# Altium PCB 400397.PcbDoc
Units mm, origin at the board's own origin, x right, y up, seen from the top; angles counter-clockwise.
Board outline 21 x 52.5 mm, 2 copper layers (Top Layer, Bottom Layer), stack 0.971 mm thick; 11 components, 17 nets, 46 pads, 17 vias.
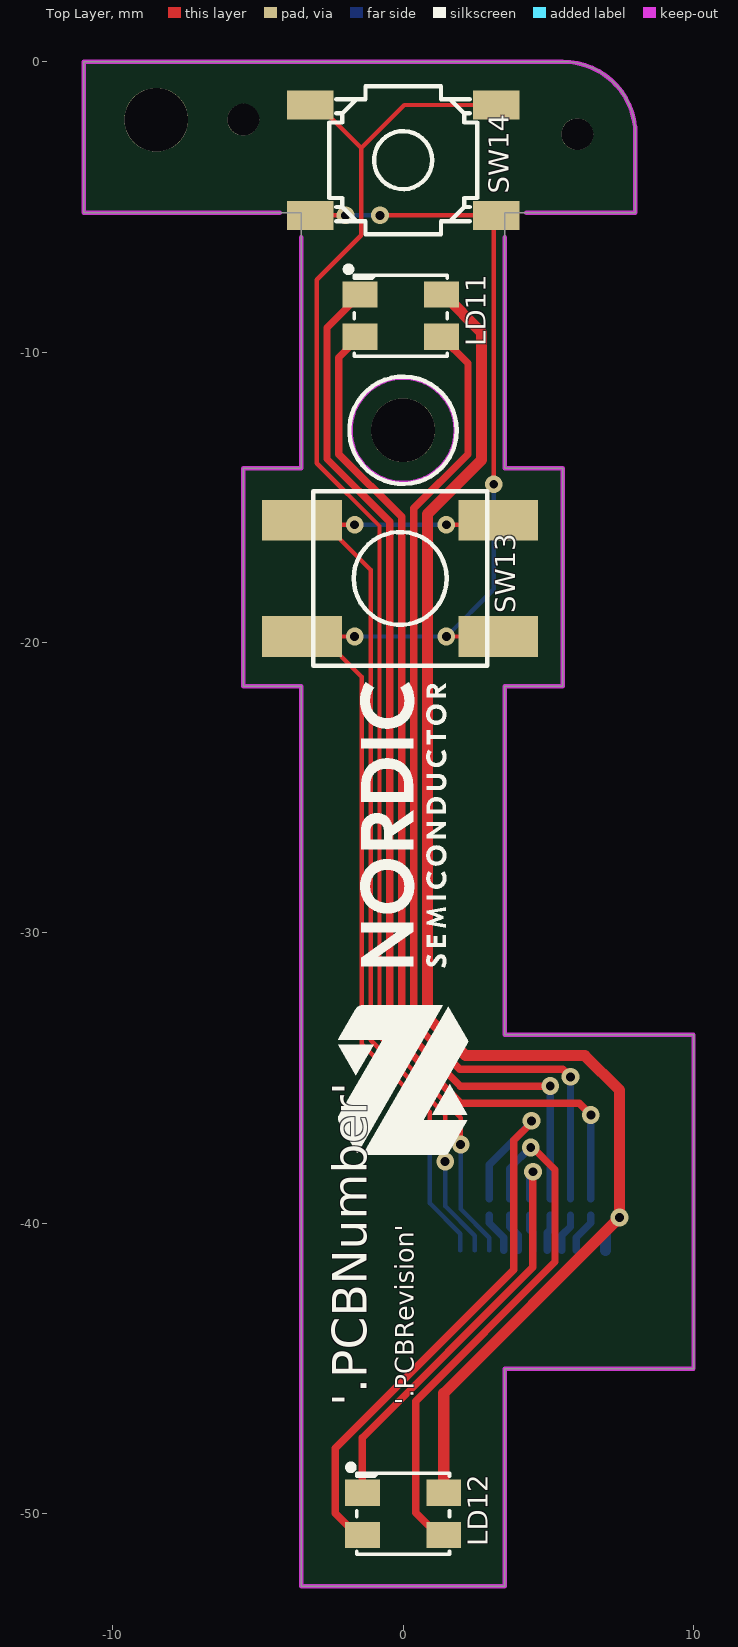
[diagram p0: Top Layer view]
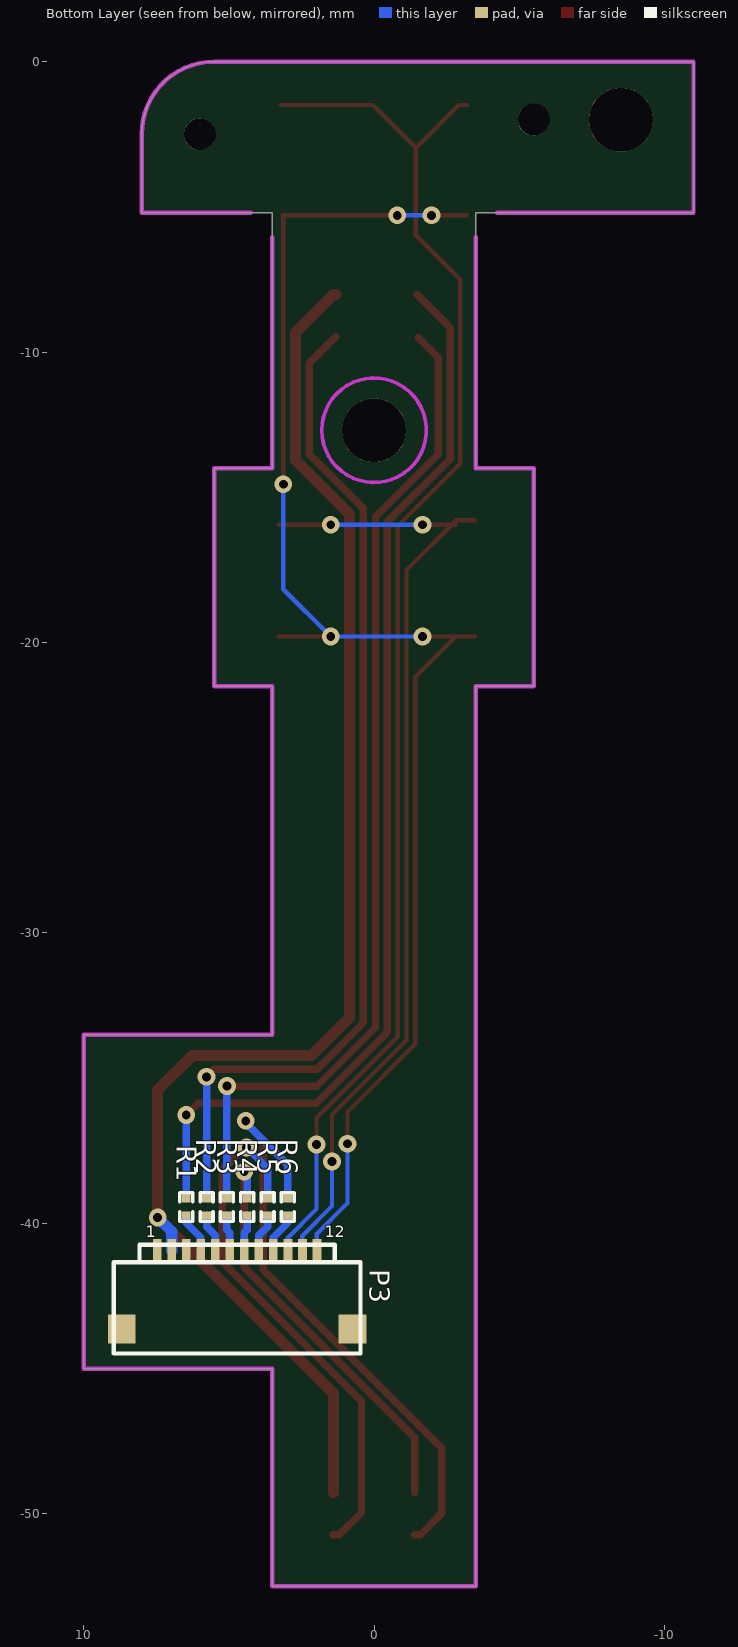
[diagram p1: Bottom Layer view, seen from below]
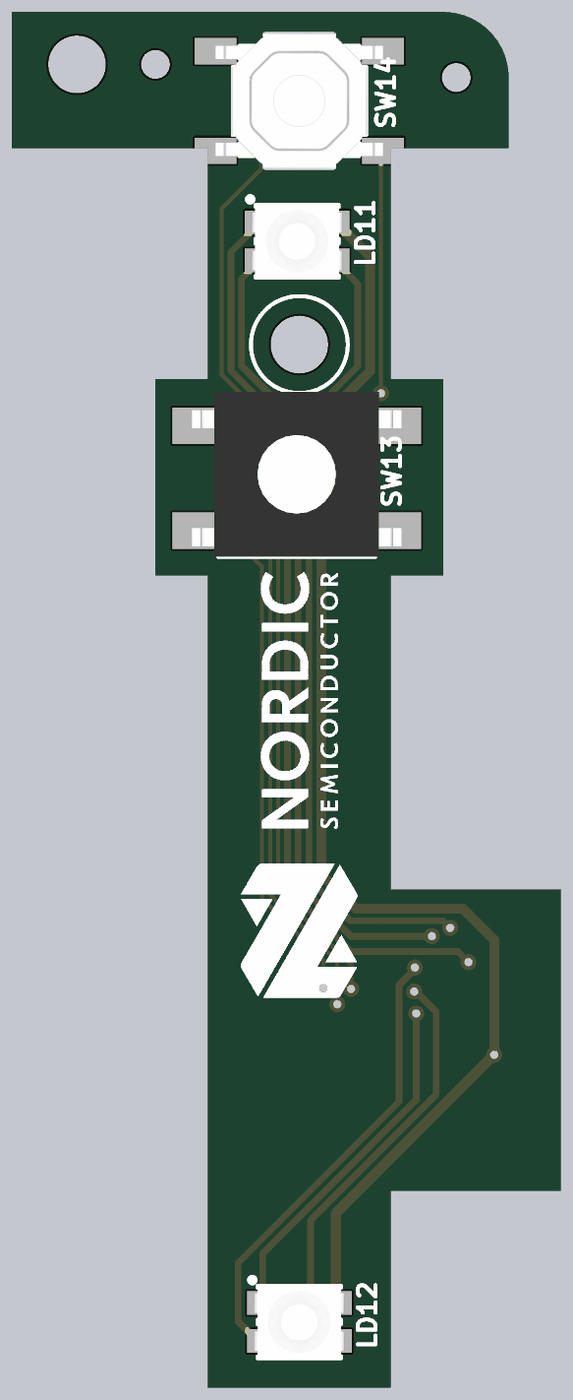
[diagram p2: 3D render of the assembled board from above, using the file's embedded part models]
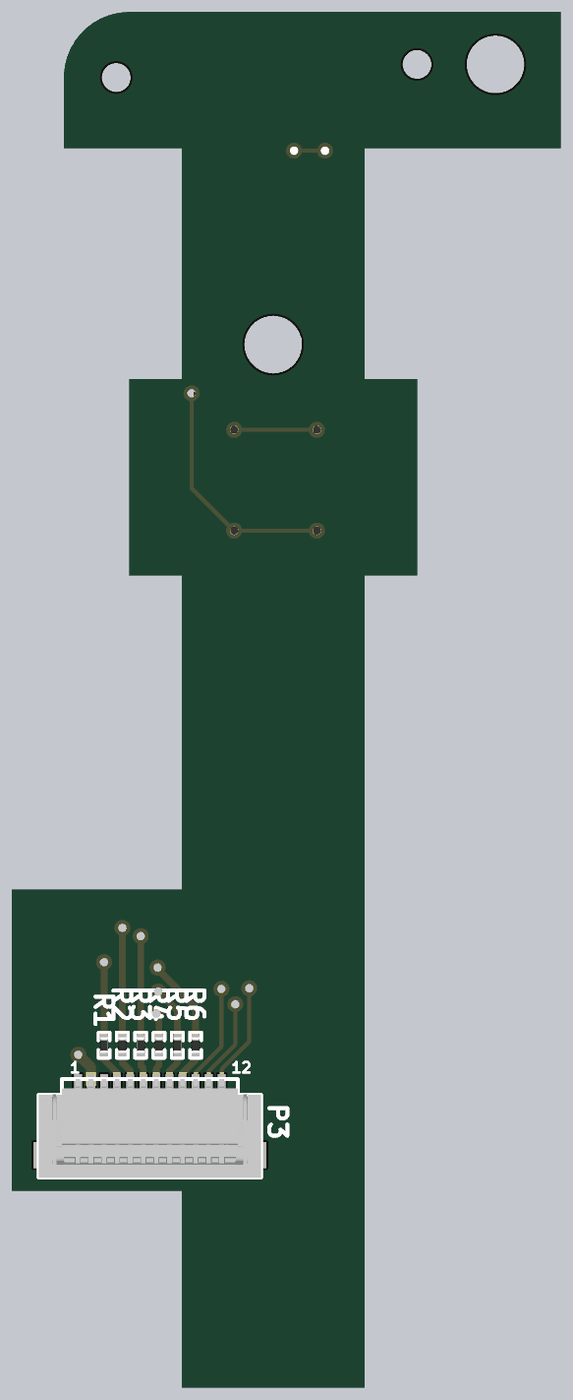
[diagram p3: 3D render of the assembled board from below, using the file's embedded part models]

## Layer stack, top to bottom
Top Solder: solder mask 0.0102, Solder Resist, Dk 3.5
Top Layer: signal copper 0.0356
Dielectric1: core 0.9, FR-4, Dk 4.8
Bottom Layer: signal copper 0.0356
Bottom Solder: solder mask 0.0102, Solder Resist, Dk 3.5

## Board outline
-3.5,-52.5 -3.5,-21.5 -5.5,-21.5 -5.5,-14 -3.5,-14 -3.5,-5.2 -11,-5.2 -11,0 5.5,0 cw(c5.5,-2.5) 8,-2.5 8,-5.2 3.5,-5.2 3.5,-14 5.5,-14 5.5,-21.5 3.5,-21.5 3.5,-33.5 10,-33.5 10,-45 3.5,-45 3.5,-52.5

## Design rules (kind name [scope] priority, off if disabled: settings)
Clearance ANT_Clerance [InNet('ANT')] p1: gap=0.127 ignorepadtopadclearanceinfootprint=FALSE except(0: Arc-Hole Track-Hole SMDPad-Hole THPad-Hole Via-Hole Fill-Hole Poly-Hole Region-Hole Text-Hole)
Clearance Polygon_Clearance [(InNamedPolygon('Top_Layer-GND')) or (InNamedPolygon('Bottom_Layer-GND'))] p2: gap=0.254 ignorepadtopadclearanceinfootprint=FALSE except(0: Arc-Hole Track-Hole SMDPad-Hole THPad-Hole Via-Hole Fill-Hole Poly-Hole Region-Hole Text-Hole)
Clearance [All] p3: gap=0.152 ignorepadtopadclearanceinfootprint=FALSE except(0: Arc-Hole Track-Hole SMDPad-Hole THPad-Hole Via-Hole Fill-Hole Poly-Hole Region-Hole Text-Hole)
ComponentClearance [All] p1 off: gap=0.254 collisioncheckmode=3 verticalgap=0.254 showdistances=FALSE
DiffPairsRouting [All] p1: maxlimit=0.15 minlimit=0.15 mostfreqgap=0.15 toplayer_minwidth=0.381 toplayer_maxwidth=0.381 toplayer_prefwidth=0.381 bottomlayer_minwidth=0.381 bottomlayer_maxwidth=0.381 bottomlayer_prefwidth=0.381 maxuncoupledlength=12.7
FabricationTestPointUsage TestPointUsage [All] p1: valid=0 allowmultiple=FALSE
FabricationTestpoint Testpoint [All] p1: side=3 testpointundercomponent=TRUE minsize=1.016 maxsize=2.54 preferedsize=1.524 minholesize=0 maxholesize=1.016 preferedholesize=0.813 testpointgrid=0.025 allowsidetop=TRUE allowsidebottom=TRUE usegrid=TRUE gridtolerance=0
Height [All] p1 off: minheight=0 maxheight=25.4 prefheight=12.7
HoleSize [All] p1: absolutevalues=TRUE maxlimit=5 minlimit=0.305 maxpercent=80.000 minpercent=20.000
MinimumAnnularRing [All] p1 off: minimumring=0.152
PolygonConnect PolygonConnect_1 [isVia and innet(gnd)] p1: connectstyle=Direct reliefconductorwidth=0.254 reliefentries=4 polygonreliefangle="90 Angle" airgapwidth=0.254
PolygonConnect [All] p2: connectstyle=Relief reliefconductorwidth=0.254 reliefentries=4 polygonreliefangle="90 Angle" airgapwidth=0.254
RoutingVias [All] p1: holewidth=0.305 width=0.61 viastyle="Through Hole" minholewidth=0.305 minwidth=0.61 maxholewidth=0.711 maxwidth=1.27
SilkToSolderMaskClearance SilkscreenOverComponentPads [IsPad] p1: minsilkscreentomaskgap=0.254 clearancetoexposedcopper=TRUE
SolderMaskExpansion [All] p1: expansion=0.076
Width [All] p1: maxlimit=2.54 minlimit=0.152 preferedwidth=0.152
23 further rules are at their usual default settings.

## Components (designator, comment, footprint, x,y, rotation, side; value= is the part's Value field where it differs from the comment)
LD11 "LED RGB" L3528_RGB -0.082,-8.749 r180 top locked
LD12 "LED RGB" L3528_RGB 0,-50 r180 top
P3 "FPC-12, 0.5mm" 10051922-1210ELF 4.716,-40.934 r180 bottom
R1 "1k" RESC0603X03L_C 6.466,-39.434 r270 bottom
R2 "470R" RESC0603X03L_C 5.766,-39.434 r270 bottom
R3 "470R" RESC0603X03L_C 5.066,-39.434 r270 bottom
R4 "1k" RESC0603X03L_C 4.366,-39.434 r270 bottom
R5 "470R" RESC0603X03L_C 3.666,-39.434 r270 bottom
R6 "470R" RESC0603X03L_C 2.966,-39.434 r270 bottom
SW13 "PB SW" Switch-PB-6.2x6.3mm-SMD -0.1,-17.794 r0 top locked
SW14 "PB SW" Switch-PB-5.1x5.1mm-SMD 0,-3.394 r180 top

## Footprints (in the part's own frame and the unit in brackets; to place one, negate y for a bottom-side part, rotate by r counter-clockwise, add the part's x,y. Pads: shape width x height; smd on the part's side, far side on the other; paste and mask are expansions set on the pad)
10051922-1210ELF [mm]
  rect 0.95x1 smd: 0(-3.975,-2.7) 0(3.975,-2.7)
  rect 0.3x0.8 smd: 1(-2.75,0) 2(-2.25,0) 3(-1.75,0) 4(-1.25,0) 5(-0.75,0) 6(-0.25,0) 7(0.25,0) 8(0.75,0) 9(1.25,0) 10(1.75,0) 11(2.25,0) 12(2.75,0)
  silkscreen extent -4.25,-3.55 4.25,0.2, body extent -4.25,-3.55 4.25,0.2, height 1.27
L3528_RGB [mm]
  rect 1.2x0.9 smd: 1(1.4,-0.725) 2(-1.4,0.725) 3(1.4,0.725) 4(-1.4,-0.725)
  silkscreen extent -1.6,-1.7 1.9,1.4, body extent -1.74,-1.39 1.76,1.41, height 1.86
RESC0603X03L_C [mm] "Chip Resistor, 2-Leads, Body 0.6x0.3mm, IPC High Density"
  rect 0.27x0.3 smd: 1(-0.285,0) 2(0.285,0)
  silkscreen extent -0.49,-0.22 0.49,0.22, body extent -0.3,-0.15 0.3,0.15, height 0.23
Switch-PB-5.1x5.1mm-SMD [mm] "5.1×5.1mm TACT Switch"
  rect 1.6x1 smd: 1(-3.2,1.9) 1(3.2,1.9) 2(-3.2,-1.9) 2(3.2,-1.9)
  silkscreen extent -2.56,-2.55 2.54,2.55, body extent -3.3,-2.6 3.2,7.2, height 1.5
Switch-PB-6.2x6.3mm-SMD [mm] "6.2×6.5mm TACT Switch, without ground connector"
  rect 2.75x1.4 smd: 1(-3.375,2) 1(3.375,2) 2(-3.375,-2) 2(3.375,-2)
  silkscreen extent -3,-3 3,3, body extent -4,-3 4,3.3, height 3.1

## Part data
LD11 LD12: library part AAA3528LSEEZGKQBKS, "3.5 x 2.8 mm Surface Mount RGB LED", Manufacturer="Kingbright Company LLC", Part number IPS=N.A., Supplier Part Number 1=754-1967-1-ND
P3: library part 10051922-1210ELF, "0.5mm pitch, bottom side contact, side entry SMD FPC connector", Manufacturer=FCI, Part number IPS=N.A., Supplier Part Number 1=609-1236-1-ND
R1 R4: library part R0201-1k0, "Resistor, ±1%, 0.05W", Part number IPS=N.A.
R2 R3 R5 R6: library part R0201-470, "Resistor, ±1%, 0.05W", Part number IPS=N.A.
SW13: library part Switch-PB-6.2x6.3mm-SMD, "Tactile Switch, SPNO, SMD, 160gf, 6.2x6.3x2.5mm", Manufacturer=Dailywell, Manufacturer Part Number=TS604VM1-025BR-R, Part number IPS=00000007812
SW14: library part Switch-PB-5.1x5.1mm-SMD, "Tactile Switch, SPNO, SMD, 160gf, 5.1x5.1x1.5mm", Manufacturer="C&K Components", Manufacturer Part Number="PTS525 SM15 SMTR2 LFS", Part number IPS=N.A., Supplier Part Number 1=CKN9104CT-ND

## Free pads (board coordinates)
  round 2.2 hole 2.2 unplated: 0(-8.5,-2) 0(0,-12.694)
  round 1.1 hole 1.1 unplated: 0(-5.5,-2) 0(6,-2.5)

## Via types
v1: diameter 0.61, hole 0.305, Top Layer to Bottom Layer, tented both sides, 17 vias

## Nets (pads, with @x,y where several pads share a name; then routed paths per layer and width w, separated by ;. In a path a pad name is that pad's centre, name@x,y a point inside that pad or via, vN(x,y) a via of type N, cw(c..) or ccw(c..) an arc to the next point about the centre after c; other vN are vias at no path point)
COL_B: P3.12 SW13.2 SW14.1 | length 51.4
  Top Layer w0.152: SW13.2@-3.475,-19.794 SW13.2@-2.813,-19.794 ; SW14.1@-3.2,-5.294 v1(-1.981,-5.294) ; v1(-1.669,-19.794) SW13.2@-2.813,-19.794 ; v1(-0.798,-5.294) SW14.1@3.122,-5.294 ; v1(0.914,-37.262) 0.914,-36.163 -1.422,-33.826 -1.422,-21.185 SW13.2@-2.813,-19.794 ; v1(1.491,-19.794) SW13.2@3.275,-19.794 ; v1(3.122,-14.552) SW14.1@3.122,-5.294 ; SW14.1@3.148,-5.294 SW14.1@3.122,-5.294
  Bottom Layer w0.152: v1(-1.981,-5.294) v1(-0.798,-5.294) ; v1(-1.669,-19.794) v1(1.491,-19.794) 3.122,-18.163 v1(3.122,-14.552) ; v1(0.914,-37.262) 0.914,-39.302 1.966,-40.354 P3.12
GND: P3.1
LED2_B: P3.9 R6.2 | length 1.4
  Bottom Layer w0.254: R6.2 2.966,-39.989 3.466,-40.489 P3.9
LED2_G: P3.8 R5.2 | length 1.3
  Bottom Layer w0.254: R5.2 3.666,-40.114 3.966,-40.414 P3.8
LED2_R: P3.7 R4.2 | length 1.3
  Bottom Layer w0.254: R4.2 4.366,-40.215 4.466,-40.315 P3.7
LED3_B: P3.6 R3.2 | length 1.3
  Bottom Layer w0.254: P3.6 4.966,-40.315 5.066,-40.215 R3.2
LED3_G: P3.5 R2.2 | length 1.3
  Bottom Layer w0.254: P3.5 5.466,-40.414 5.766,-40.114 R2.2
LED3_R: P3.4 R1.2 | length 1.4
  Bottom Layer w0.254: P3.4 5.966,-40.489 6.466,-39.989 R1.2
NetLD11_1: LD11.1 R1.1 | length 37.7
  Top Layer w0.254: LD11.1 -2.618,-9.16 -2.618,-13.681 -0.457,-15.842 -0.457,-33.426 1.981,-35.865 6.064,-35.865 v1(6.466,-36.267)
  Bottom Layer w0.254: R1.1 v1(6.466,-36.267)
NetLD11_2: LD11.2 R2.1 | length 35.1
  Top Layer w0.254: LD11.2 2.233,-10.39 2.233,-13.517 0.368,-15.382 0.368,-33.102 1.955,-34.689 5.498,-34.689 v1(5.766,-34.957)
  Bottom Layer w0.254: R2.1 v1(5.766,-34.957)
NetLD11_3: LD11.3 R3.1 | length 34.8
  Top Layer w0.254: LD11.3@-1.526,-9.5 -2.212,-10.186 -2.212,-13.513 -0.051,-15.674 -0.051,-33.258 1.965,-35.273 v1(5.066,-35.273)
  Bottom Layer w0.254: R3.1 v1(5.066,-35.273)
NetLD12_1: LD12.1 R4.1 | length 14.5
  Top Layer w0.254: LD12.1 -1.4,-47.383 4.47,-41.513 v1(4.47,-38.224)
  Bottom Layer w0.254: R4.1 4.366,-38.329 v1(4.47,-38.224)
NetLD12_2: LD12.2 R5.1 | length 18.3
  Top Layer w0.254: LD12.2 1.195,-50.725 0.432,-49.962 0.432,-46.126 5.232,-41.326 5.232,-38.16 4.458,-37.386 v1(4.394,-37.386)
  Bottom Layer w0.254: R5.1 3.666,-38.113 v1(4.394,-37.386)
NetLD12_3: LD12.3 R6.1 | length 20.9
  Top Layer w0.254: LD12.3 -1.599,-50.725 -2.337,-49.987 -2.337,-47.746 3.809,-41.599 3.809,-37.144 4.419,-36.534 v1(4.419,-36.471)
  Bottom Layer w0.254: R6.1 2.966,-37.987 4.482,-36.471 v1(4.419,-36.471)
ROW_3: P3.11 SW13.1 | length 34.7
  Top Layer w0.152: SW13.1@-2.813,-15.947 v1(-1.669,-15.947) ; SW13.1@-2.813,-15.794 -3.475,-15.794 -2.826,-15.794 -1.118,-17.502 -1.118,-33.7 1.448,-36.265 v1(1.448,-37.871) ; v1(1.491,-15.947) SW13.1@3.275,-15.947
  Bottom Layer w0.152: v1(-1.669,-15.947) v1(1.491,-15.947) ; v1(1.448,-37.871) 1.448,-39.405 2.466,-40.423 P3.11
ROW_4: P3.10 SW14.2 | length 48.7
  Top Layer w0.152: SW14.2@-3.2,-1.494 -2.92,-1.494 -1.441,-2.973 ; v1(1.981,-37.287) 1.981,-36.368 -0.813,-33.574 -0.813,-15.989 -2.974,-13.828 -2.974,-7.512 -1.441,-5.978 -1.441,-2.973 ; SW14.2@3.2,-1.494 0.039,-1.494 -1.441,-2.973
  Bottom Layer w0.152: v1(1.981,-37.287) 1.981,-39.507 2.966,-40.492 P3.10
VDD_LED: LD11.4 LD12.4 P3.2 | length 51.6
  Top Layer w0.381: LD11.4 1.403,-8.024 2.703,-9.325 2.703,-13.712 0.838,-15.577 0.838,-32.908 2.15,-34.219 6.254,-34.219 7.451,-35.416 v1(7.451,-39.8) 1.4,-45.851 LD12.4
  Bottom Layer w0.381: P3.2 6.966,-40.285 v1(7.451,-39.8)
pads on no net: P3.0 P3.3

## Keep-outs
Keep-Out Layer:
  circle w0.127: c0,-12.694 r1.8
  lines w0.152: -4.242,-5.2 -11,-5.2 -11,0 5.5,0 cw(c5.5,-2.5) 8,-2.5 8,-5.2 4.242,-5.2 ; -3.5,-6.045 -3.5,-14 -5.5,-14 -5.5,-21.5 -3.5,-21.5 -3.5,-50 -3.5,-52.5 3.5,-52.5 3.5,-45 10,-45 10,-33.5 3.5,-33.5 3.5,-21.5 5.5,-21.5 5.5,-14 3.5,-14 3.5,-6.045

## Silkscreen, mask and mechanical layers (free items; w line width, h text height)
Top Overlay:
  drawing of 24 lines, arcs and shapes, not listed
  text "'.PCBRevision'" at 0.365,-46.253 h0.64 r90
  text "'.PCBNumber'" at -0.854,-46.304 h2.03 r90
Board Outline:
  lines w0.152: -5.5,-21.5 -3.5,-21.5 ; -5.5,-21.5 -5.5,-21.5 ; -5.5,-21.5 -5.5,-14 ; -5.5,-14 -5.5,-14 ; -5.5,-14 -3.5,-14 -3.5,-5.2 -11,-5.2 -11,0 5.5,0 cw(c5.5,-2.5) 8,-2.5 8,-5.2 3.5,-5.2 3.5,-14 5.5,-14 5.5,-21.5 3.5,-21.5 3.5,-33.5 10,-33.5 10,-45 3.5,-45 3.5,-52.5 -3.5,-52.5 -3.5,-50 -3.5,-21.5 ; -3.5,-21.5 -3.5,-21.5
